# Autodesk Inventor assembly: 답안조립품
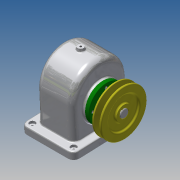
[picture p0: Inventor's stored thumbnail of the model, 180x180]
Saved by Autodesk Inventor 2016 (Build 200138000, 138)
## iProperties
Created: 2016-10
Part Number: 답안조립품
Document SubType Name: Assembly
Designer: Administrator
Author: Administrator
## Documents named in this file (15)
- D:\461007V1001\답안조립품.iam
- D:\461007V1001\본체.ipt
- D:\461007V1001\베어링 6203.ipt
- D:\461007V1001\볼트 M3 x 8.ipt
- D:\461007V1001\뒤커버.ipt
- D:\461007V1001\스퍼기어.ipt
- D:\461007V1001\축.ipt
- D:\461007V1001\키 - 6 x 6 x 22.ipt
- D:\461007V1001\부시.ipt
- D:\461007V1001\앞커버.ipt
- D:\461007V1001\오일씰 28 40 8.ipt
- D:\461007V1001\키 - 5 x 5 x 18.ipt
- D:\461007V1001\멈춤나사 - M4x10.ipt
- D:\461007V1001\볼트 M3 x 10.ipt
- D:\461007V1001\V-벨트풀리.ipt
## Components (9 placed, 3 different names)
1. V-벨트풀리:1
2. ISO 4762 M3 x 8:1
3. ISO 4762 M3 x 8:2
4. ISO 4762 M3 x 8:3
5. ISO 4762 M3 x 8:4
6. ISO 4762 M3 x 10:1
7. ISO 4762 M3 x 10:2
8. ISO 4762 M3 x 10:3
9. ISO 4762 M3 x 10:4
